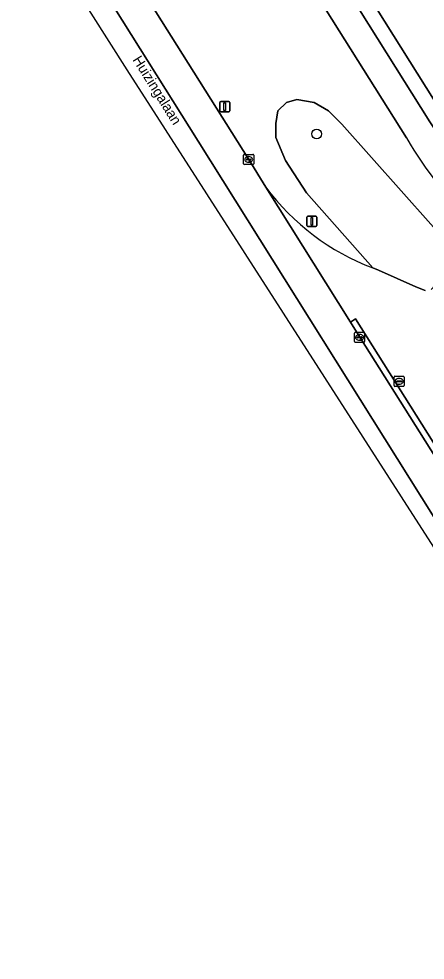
# Model space of a CAD drawing. Extents: x 160077 to 160948, y 386481 to 387498.
# Drawn here: x 160182.2 to 160222.5, y 387050.3 to 387143.6 of the extents above; entities that cross this region are included whole.
import ezdxf

# ---------------------------------------------------------------- set-up
doc = ezdxf.new("R2010")
doc.units = 0
for name, color, linetype in [('IMGEO_Berm_groen', 7, 'Continuous'), ('IMGEO_Boom', 7, 'Continuous'), ('IMGEO_Fietspad_gesloten', 7, 'Continuous'), ('IMGEO_Groenvoorziening', 7, 'Continuous'), ('IMGEO_Kolk', 7, 'Continuous'), ('IMGEO_Lichtmast', 7, 'Continuous'), ('IMGEO_Openbare_ruimte_label', 7, 'Continuous'), ('IMGEO_OVBaan_gesloten', 7, 'Continuous'), ('IMGEO_Rijbaan_regionaal_gesloten', 7, 'Continuous'), ('IMGEO_Verkeersbordpaal', 7, 'Continuous'), ('IMGEO_Verkeerseiland_open', 7, 'Continuous'), ('IMGEO_Voetpad_open', 7, 'Continuous')]:
    doc.layers.add(name, color=color, linetype=linetype)

msp = doc.modelspace()

# ---------------------------------------------------------------- linework, layer by layer
at = {"layer": 'IMGEO_Berm_groen'}
for points in [[(160220.594, 387131.778), (160198.581, 387166.822), (160161.015, 387226.623)], [(160169.034, 387186.827), (160173.425, 387179.881), (160184.266, 387162.563), (160194.633, 387146.088), (160204.971, 387129.647), (160206.665, 387126.914)], [(160217.256, 387118.893), (160210.698, 387126.331), (160208.62, 387129.543), (160207.676, 387131.809), (160207.676, 387133.226), (160207.865, 387134.454), (160208.715, 387135.304), (160209.754, 387135.588), (160211.454, 387135.304), (160212.871, 387134.454), (160214.193, 387133.132), (160225.948, 387119.941), (160226.83, 387120.899)]]:
    msp.add_lwpolyline(points, dxfattribs=at)
for centre, radius, start, end in [((160258.895, 387154.487), 44.527, 210.66372, 225.31635), ((160225.764, 387141.13), 23.809, 216.66149, 249.06222)]:
    msp.add_arc(centre, radius, start, end, dxfattribs=at)
at = {"layer": 'IMGEO_Boom'}
msp.add_circle((160211.701, 387132.174), 0.489, dxfattribs=at)
at = {"layer": 'IMGEO_Fietspad_gesloten'}
for points in [[(160223.762, 387132.086), (160222.926, 387133.369), (160185.895, 387192.376), (160184.005, 387195.408), (160180.666, 387200.687), (160159.923, 387233.732), (160141.59, 387262.907), (160139.072, 387265.739)], [(160136.342, 387264.367), (160139.625, 387260.516), (160141.252, 387258.195), (160161.015, 387226.623), (160198.581, 387166.822), (160220.594, 387131.778)]]:
    msp.add_lwpolyline(points, dxfattribs=at)
msp.add_arc((160258.895, 387154.487), 44.527, 210.66372, 225.31635, dxfattribs=at)
at = {"layer": 'IMGEO_Groenvoorziening'}
for points in [[(160235.799, 387137.046), (160230.812, 387134.941), (160208.795, 387187.088), (160213.806, 387189.204), (160211.661, 387194.284), (160216.461, 387196.334), (160216.109, 387197.157), (160218.173, 387198.038), (160218.06, 387198.303), (160218.439, 387198.463), (160225.112, 387201.343), (160215.32, 387216.878), (160211.947, 387214.771), (160192.529, 387202.664), (160184.423, 387197.569), (160187.198, 387193.134), (160224.187, 387134.187), (160225.336, 387132.427)], [(160214.193, 387133.132), (160212.871, 387134.454), (160211.454, 387135.304), (160209.754, 387135.588), (160208.715, 387135.304), (160207.865, 387134.454), (160207.676, 387133.226), (160207.676, 387131.809), (160208.62, 387129.543), (160210.698, 387126.331), (160217.256, 387118.893), (160217.834, 387118.68), (160221.518, 387117.036), (160222.457, 387116.666)], [(160223.035, 387116.777), (160225.948, 387119.941), (160214.193, 387133.132)]]:
    msp.add_lwpolyline(points, dxfattribs=at)
at = {"layer": 'IMGEO_Kolk'}
for p, q in [((160204.47, 387129.221), (160204.47, 387130.073)), ((160204.545, 387130.147), (160205.397, 387130.147)), ((160204.729, 387129.641), (160204.729, 387129.653)), ((160205.167, 387129.604), (160204.769, 387129.604)), ((160204.772, 387129.69), (160205.17, 387129.69)), ((160204.981, 387129.367), (160204.956, 387129.367)), ((160204.958, 387129.927), (160204.983, 387129.927)), ((160205.213, 387129.653), (160205.213, 387129.641)), ((160205.471, 387130.073), (160205.471, 387129.221)), ((160205.397, 387129.147), (160204.545, 387129.147)), ((160215.458, 387111.592), (160215.458, 387112.444)), ((160215.533, 387112.518), (160216.385, 387112.518)), ((160216.459, 387112.444), (160216.459, 387111.592)), ((160216.385, 387111.518), (160215.533, 387111.518)), ((160215.717, 387112.012), (160215.717, 387112.024)), ((160216.155, 387111.975), (160215.757, 387111.975)), ((160215.76, 387112.061), (160216.158, 387112.061)), ((160215.969, 387111.738), (160215.944, 387111.738)), ((160215.946, 387112.298), (160215.971, 387112.298)), ((160216.201, 387112.024), (160216.201, 387112.012)), ((160219.375, 387107.232), (160219.375, 387108.084)), ((160219.45, 387108.158), (160220.302, 387108.158)), ((160219.863, 387107.938), (160219.888, 387107.938)), ((160220.376, 387108.084), (160220.376, 387107.232)), ((160220.302, 387107.158), (160219.45, 387107.158)), ((160219.634, 387107.652), (160219.634, 387107.664)), ((160220.072, 387107.615), (160219.674, 387107.615)), ((160219.677, 387107.701), (160220.075, 387107.701)), ((160219.886, 387107.378), (160219.861, 387107.378)), ((160220.118, 387107.664), (160220.118, 387107.652))]:
    msp.add_line(p, q, dxfattribs=at)
for points in [[(160204.47, 387129.221), (160204.47, 387130.073)], [(160204.545, 387130.147), (160205.397, 387130.147)], [(160205.471, 387130.073), (160205.471, 387129.221)], [(160205.397, 387129.147), (160204.545, 387129.147)], [(160215.458, 387111.592), (160215.458, 387112.444)], [(160215.533, 387112.518), (160216.385, 387112.518)], [(160216.459, 387112.444), (160216.459, 387111.592)], [(160216.385, 387111.518), (160215.533, 387111.518)], [(160219.375, 387107.232), (160219.375, 387108.084)], [(160219.45, 387108.158), (160220.302, 387108.158)], [(160220.376, 387108.084), (160220.376, 387107.232)], [(160220.302, 387107.158), (160219.45, 387107.158)]]:
    msp.add_lwpolyline(points, dxfattribs=at)
for centre, radius, start, end in [((160204.547, 387130.071), 0.0765, 91.55205, 178.44795), ((160204.547, 387130.071), 0.0765, 91.55205, 178.44795), ((160204.547, 387129.223), 0.0765, 181.55205, 268.44795), ((160204.547, 387129.223), 0.0765, 181.55205, 268.44795), ((160204.769, 387129.65), 0.0403, 85.87752, 175.75265), ((160204.766, 387129.64), 0.0366, 178.93798, 274.71019), ((160205.17, 387129.647), 0.043, 264.86636, 352.45326), ((160205.174, 387129.652), 0.0386, 1.73085, 96.63898), ((160205.395, 387130.071), 0.0765, 1.55205, 88.44795), ((160205.395, 387130.071), 0.0765, 1.55205, 88.44795), ((160205.395, 387129.223), 0.0765, 271.55205, 358.44795), ((160205.395, 387129.223), 0.0765, 271.55205, 358.44795), ((160215.535, 387112.442), 0.0765, 91.55205, 178.44795), ((160215.535, 387112.442), 0.0765, 91.55205, 178.44795), ((160216.383, 387112.442), 0.0765, 1.55205, 88.44795), ((160216.383, 387112.442), 0.0765, 1.55205, 88.44795), ((160215.535, 387111.594), 0.0765, 181.55205, 268.44795), ((160215.535, 387111.594), 0.0765, 181.55205, 268.44795), ((160215.757, 387112.021), 0.0403, 85.87752, 175.75265), ((160215.754, 387112.011), 0.0366, 178.93798, 274.71019), ((160216.158, 387112.018), 0.043, 264.86636, 352.45326), ((160216.162, 387112.023), 0.0386, 1.73085, 96.63898), ((160216.383, 387111.594), 0.0765, 271.55205, 358.44795), ((160216.383, 387111.594), 0.0765, 271.55205, 358.44795), ((160219.452, 387108.082), 0.0765, 91.55205, 178.44795), ((160219.452, 387108.082), 0.0765, 91.55205, 178.44795), ((160220.3, 387108.082), 0.0765, 1.55205, 88.44795), ((160220.3, 387108.082), 0.0765, 1.55205, 88.44795), ((160219.452, 387107.234), 0.0765, 181.55205, 268.44795), ((160219.452, 387107.234), 0.0765, 181.55205, 268.44795), ((160219.674, 387107.661), 0.0403, 85.87752, 175.75265), ((160219.671, 387107.651), 0.0366, 178.93798, 274.71019), ((160220.075, 387107.658), 0.043, 264.86636, 352.45326), ((160220.079, 387107.663), 0.0386, 1.73085, 96.63898), ((160220.3, 387107.234), 0.0765, 271.55205, 358.44795), ((160220.3, 387107.234), 0.0765, 271.55205, 358.44795)]:
    msp.add_arc(centre, radius, start, end, dxfattribs=at)
for centre, major_axis, ratio, start_param, end_param in [((160204.957, 387129.647), (-0.387, 0.002), 0.722429, 4.712389, 7.853982), ((160204.982, 387129.647), (-0.39, 0.002), 0.717154, 1.570796, 4.712389), ((160215.945, 387112.018), (-0.387, 0.002), 0.722429, 4.712389, 7.853982), ((160215.97, 387112.018), (-0.39, 0.002), 0.717154, 1.570796, 4.712389), ((160219.862, 387107.658), (-0.387, 0.002), 0.722429, 4.712389, 7.853982), ((160219.887, 387107.658), (-0.39, 0.002), 0.717154, 1.570796, 4.712389)]:
    msp.add_ellipse(centre, major_axis=major_axis, ratio=ratio, start_param=start_param, end_param=end_param, dxfattribs=at)
at = {"layer": 'IMGEO_Lichtmast'}
for p, q in [((160202.1, 387134.476), (160202.1, 387135.276)), ((160202.1, 387135.276), (160202.1, 387134.476)), ((160202.2, 387135.376), (160202.99, 387135.376)), ((160202.99, 387135.376), (160202.2, 387135.376)), ((160203.09, 387135.276), (160203.09, 387134.476)), ((160203.09, 387134.476), (160203.09, 387135.276)), ((160202.99, 387134.376), (160202.2, 387134.376)), ((160202.2, 387134.376), (160202.99, 387134.376))]:
    msp.add_line(p, q, dxfattribs=at)
msp.add_lwpolyline([(160202.52, 387135.251), (160202.67, 387135.251), (160202.67, 387134.501), (160202.52, 387134.501), (160202.52, 387135.251)], dxfattribs=at)
for centre, start, end in [((160202.2, 387135.276), 90, 180), ((160202.2, 387135.276), 90, 180), ((160202.99, 387135.276), 0, 90), ((160202.99, 387135.276), 360, 90), ((160202.2, 387134.476), 180, 270), ((160202.2, 387134.476), 180, 270), ((160202.99, 387134.476), 270, 0), ((160202.99, 387134.476), 270, 0)]:
    msp.add_arc(centre, 0.1, start, end, dxfattribs=at)
at = {"layer": 'IMGEO_OVBaan_gesloten'}
for points in [[(160118.75, 387255.247), (160163.481, 387184.835), (160192.901, 387138.525), (160266.84, 387023.396), (160283.596, 386998.712), (160314.258, 386953.544)], [(160248.244, 387054.606), (160224.562, 387092.222), (160199.952, 387131.452), (160165.124, 387186.911), (160140.996, 387225.337)]]:
    msp.add_lwpolyline(points, dxfattribs=at)
at = {"layer": 'IMGEO_Rijbaan_regionaal_gesloten'}
for points in [[(160140.996, 387225.337), (160165.124, 387186.911), (160199.952, 387131.452), (160224.562, 387092.222), (160248.244, 387054.606)], [(160294.047, 386992.128), (160288.226, 387000.827), (160263.871, 387037.139), (160254.851, 387050.522), (160254.817, 387050.572), (160254.143, 387051.583), (160251.822, 387055.11), (160244.754, 387066.304), (160234.407, 387082.756), (160224.918, 387097.824), (160215.991, 387112.053), (160215.055, 387113.519), (160206.665, 387126.914), (160204.971, 387129.647), (160194.633, 387146.088), (160184.266, 387162.563), (160173.425, 387179.881), (160169.034, 387186.827)]]:
    msp.add_lwpolyline(points, dxfattribs=at)
at = {"layer": 'IMGEO_Verkeersbordpaal'}
for p, q in [((160210.726, 387123.115), (160210.726, 387123.915)), ((160210.726, 387123.915), (160210.726, 387123.115)), ((160210.826, 387124.015), (160211.616, 387124.015)), ((160211.616, 387124.015), (160210.826, 387124.015)), ((160211.716, 387123.915), (160211.716, 387123.115)), ((160211.716, 387123.115), (160211.716, 387123.915)), ((160211.616, 387123.015), (160210.826, 387123.015)), ((160210.826, 387123.015), (160211.616, 387123.015))]:
    msp.add_line(p, q, dxfattribs=at)
msp.add_lwpolyline([(160211.146, 387123.89), (160211.296, 387123.89), (160211.296, 387123.14), (160211.146, 387123.14), (160211.146, 387123.89)], dxfattribs=at)
for centre, start, end in [((160210.826, 387123.915), 90, 180), ((160210.826, 387123.915), 90, 180), ((160211.616, 387123.915), 0, 90), ((160211.616, 387123.915), 360, 90), ((160210.826, 387123.115), 180, 270), ((160210.826, 387123.115), 180, 270), ((160211.616, 387123.115), 270, 0), ((160211.616, 387123.115), 270, 0)]:
    msp.add_arc(centre, 0.1, start, end, dxfattribs=at)
at = {"layer": 'IMGEO_Verkeerseiland_open'}
msp.add_lwpolyline([(160235.362, 387082.695), (160235.14, 387083.003), (160233.74, 387084.946), (160215.564, 387113.853), (160215.055, 387113.519), (160215.991, 387112.053), (160224.918, 387097.824), (160234.407, 387082.756), (160244.754, 387066.304), (160251.822, 387055.11), (160254.143, 387051.583), (160254.817, 387050.572), (160254.851, 387050.522)], dxfattribs=at)
at = {"layer": 'IMGEO_Voetpad_open'}
for points in [[(160225.336, 387132.427), (160224.187, 387134.187), (160187.198, 387193.134), (160184.423, 387197.569)], [(160184.005, 387195.408), (160185.895, 387192.376), (160222.926, 387133.369), (160223.762, 387132.086)], [(160206.665, 387126.914), (160215.055, 387113.519), (160215.564, 387113.853), (160233.74, 387084.946), (160235.14, 387083.003), (160238.503, 387085.126), (160239.259, 387085.603), (160239.421, 387085.705), (160223.826, 387110.491)], [(160222.457, 387116.666), (160221.518, 387117.036), (160217.834, 387118.68), (160217.256, 387118.893)]]:
    msp.add_lwpolyline(points, dxfattribs=at)
msp.add_arc((160225.764, 387141.13), 23.809, 216.66149, 249.06222, dxfattribs=at)

# ---------------------------------------------------------------- texts
at = {"layer": 'IMGEO_Openbare_ruimte_label'}
msp.add_text('Huizingalaan', height=1, rotation=302.08436, dxfattribs=at).set_placement((160193.429, 387139.525))

doc.saveas('drawing.dxf')
